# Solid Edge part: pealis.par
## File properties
Author: Cymax
Template: Normal.par
Last saved by: Cymax
Revision: 21
Application: Solid Edge
Accuracy: 0,990
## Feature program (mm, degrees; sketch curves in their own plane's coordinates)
sketch used by "unnamed Protrusion 1" plane through (0, 0, 0) normal (0, 0, 1) x-axis (1, 0, 0)
  line (-3600, 500) -> (-3600, -500)
  line (1000, 1000) -> (-1000, 1000)
  line (1000, -1000) -> (-1000, -1000)
  arc centre (1000, -2880) radius 3880 from (1000, 1000) to (3600, 0) cw
  arc centre (1000, 2880) radius 3880 from (1000, -1000) to (3600, 0) ccw
  arc centre (-1000, -6010) radius 7010 from (-1000, 1000) to (-3600, 500) ccw
  arc centre (-1000, 6010) radius 7010 from (-1000, -1000) to (-3600, -500) cw
extrude "unnamed Protrusion 1" add finite 45 along -normal
logasc func "Lip_Groove_1"  LipOrGrooveWidth = 40 mm; LipOrGrooveHeight = 100 mm
fillet "Round_5" radius 130
sketch for "ExtrudedProtrusion_4" plane through (-26.1302, 0, 0) normal (0, 0, 1) x-axis (-1, 0, 0)
  line (0, 0) -> (0, 0)
  line (-1896.6609, -700) -> (1544.4006, -720.5308)
  line (-1896.6609, 700) -> (-1896.6609, -700)
  line (1544.4006, 720.5308) -> (-1896.6609, 700)
  line (1544.4006, 435) -> (1544.4006, 720.5308)
  line (2940.9751, 435) -> (1544.4006, 435)
  line (2940.9751, -435) -> (2940.9751, 435)
  line (2940.9751, -435) -> (1544.4006, -435)
  line (1544.4006, -435) -> (1544.4006, -720.5308)
extrude "ExtrudedProtrusion_4" add finite 1000 along +normal
sketch for "ExtrudedCutout_3" plane through (0, 0, 0) normal (1, 0, 0) x-axis (0, 1, 0)
  line (745.757, 317.5672) -> (849.4238, 317.5672)
  line (745.757, 317.5672) -> (744.0159, 324.6437)
  arc centre (-453.8381, 29.9336) radius 1233.5754 from (315.9537, 993.8469) to (744.0159, 324.6437) cw
  line (315.9537, 993.8469) -> (170.103, 1110.3249)
  line (-170.103, 1110.3249) -> (170.103, 1110.3249)
  line (-316.9039, 993.0881) -> (-170.103, 1110.3249)
  arc centre (450.6568, 31.9686) radius 1230 from (-743.7254, 325.8245) to (-316.9039, 993.0881) cw
  line (-745.757, 317.5672) -> (-743.7254, 325.8245)
  line (-745.757, 317.5672) -> (-842.6011, 317.5672)
extrude "ExtrudedCutout_3" cut finite 7010.3265 symmetric
sketch for "unnamed Cutout 1" plane through (0, 0, 0) normal (0, -1, 0) x-axis (1, 0, 0)
  line (1957.4005, 0) -> (2691.2115, 297.8266)
  arc centre (-1595.7152, -3073.6527) radius 4698.0818 from (278.8141, 1234.26) to (1957.4005, 0) cw
  line (278.8141, 1234.26) -> (278.8141, 2014.4516)
  line (-2000.4389, 1220.5533) -> (278.8141, 2014.4516)
  line (-2417.9781, 349.241) -> (-2000.4389, 1220.5533)
  line (-3102.9585, 349.241) -> (-2417.9781, 349.241)
extrude "unnamed Cutout 1" cut finite 1529.4835 symmetric
sketch for "ExtrudedCutout_6" plane through (0, 0, 0) normal (0, -1, 0) x-axis (1, 0, 0)
  line (-2132.8174, 356.3644) -> (-1980.9087, 356.3644)
  line (-1980.9087, 356.3644) -> (-1980.9087, 456.1988)
  line (-1980.9087, 456.1988) -> (-1891.0829, 456.1988)
  line (-1891.0829, 456.1988) -> (-1891.0829, 563.1934)
  line (-1891.0829, 563.1934) -> (-1781.2573, 563.1934)
  line (-1781.2573, 563.1934) -> (-1781.2573, 661.8189)
  line (-1781.2573, 661.8189) -> (-1681.4316, 661.8189)
  line (-1681.4316, 661.8189) -> (-1681.4316, 754.1643)
  line (-1681.4316, 754.1643) -> (-1551.2242, 754.1643)
  line (-1551.2242, 754.1643) -> (-1551.2242, 867.0108)
  line (-1551.2242, 867.0108) -> (-1453.5417, 867.0108)
  line (-1453.5417, 867.0108) -> (-1453.5417, 1000.2115)
extrude "ExtrudedCutout_6" cut finite 250.1957 symmetric
thinwall "Thinwall_7"  Thickness = 250 mm
sketch used by "unnamed Cutout 2" plane through (0, 0, -45) normal (0, 0, -1) x-axis (-1, 0, 0)
extrude "unnamed Cutout 2" cut to key point along -normal
chamfer "Chamfer_7" setback 85
fillet "Round_6" radius 200
sketch for "ExtrudedCutout_9" plane through (0, 0, -45) normal (0, 0, -1) x-axis (-1, 0, 0)
extrude "ExtrudedCutout_9" cut finite 1496.2197 along -normal
swept protrusion "SweptProtrusion_6"
helix protrusion "HelixProtrusion_1"  Pitch = 50 mm
sketch for "unnamed Protrusion 2" plane through (0, 0, -45) normal (0, 0, -1) x-axis (-1, 0, 0)
  arc centre (-1000, 2880) radius 3880 from (-3505.0582, -82.9518) to (-3600, 0) cw
  arc centre (-1000, -2880) radius 3880 from (-3505.0582, 82.9518) to (-3600, 0) ccw
  line (-3505.0582, 82.9518) -> (-3505.0582, -82.9518)
extrude "unnamed Protrusion 2" add to key point along +normal
fillet "Round_7" radius 20
sketch for "ExtrudedCutout_10" plane through (-26.1302, 0, 0) normal (0, 0, 1) x-axis (-1, 0, 0)
  arc centre (-1026.1302, 2880) radius 3780 from (-1026.1302, -900) to (-3474.3948, 0) cw
  arc centre (-1026.1302, -2880) radius 3780 from (-1026.1302, 900) to (-3474.3948, 0) ccw
  line (-1026.1302, 900) -> (973.8698, 900)
  arc centre (973.8698, -6010) radius 6910 from (973.8698, 900) to (3473.8698, 431.9019) cw
  line (3473.8698, -431.9019) -> (3473.8698, 431.9019)
  arc centre (973.8698, 6010) radius 6910 from (973.8698, -900) to (3473.8698, -431.9019) ccw
  line (-1026.1302, -900) -> (973.8698, -900)
extrude "ExtrudedCutout_10" cut finite 80 symmetric
sketch for "ExtrudedProtrusion_8" #1 plane through (0, 0, -45) normal (0, 0, -1) x-axis (-1, 0, 0)
  circle centre (1600, -600) radius 75
sketch for "ExtrudedProtrusion_8" #2 plane through (0, 0, -45) normal (0, 0, -1) x-axis (-1, 0, 0)
  circle centre (1600, 600) radius 75
sketch for "ExtrudedProtrusion_8" #3 plane through (0, 0, -45) normal (0, 0, -1) x-axis (-1, 0, 0)
  circle centre (-1600, 600) radius 75
sketch for "ExtrudedProtrusion_8" #4 plane through (0, 0, -45) normal (0, 0, -1) x-axis (-1, 0, 0)
  circle centre (-1600, -600) radius 75
extrude "ExtrudedProtrusion_8" add finite 100 along +normal
sketch for "ExtrudedProtrusion_9" plane through (-4144.3179, 0, -757.9714) normal (-0.681543, 0, -0.731778) x-axis (0, 1, 0)
  circle centre (0, 0) radius 20
extrude "ExtrudedProtrusion_9" add to key point along -normal  Profile_Plane1_FractionOfCurve = 0
sketch for "ExtrudedProtrusion_10" plane through (-3809.9756, 0, -398.9857) normal (-0.731778, 0, 0.681543) x-axis (0, 1, 0)
  line (-5, 490.5665) -> (5, 490.5665)
  line (5, 490.5665) -> (5, -209.4335)
  line (5, -209.4335) -> (-5, -209.4335)
  line (-5, -209.4335) -> (-5, 490.5665)
extrude "ExtrudedProtrusion_10" add finite 30 along +normal
Other named dimensions: "ExtrudedSurface_3": FiniteDepth = 3246.0356 mm | "ExtrudedSurface_4": FiniteDepth = 2943.7397 mm | "ExtrudedSurface_5": FiniteDepth = 9148.0586 mm
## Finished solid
Body 1: sheet body, 1 face, 4 edges, 4 vertices.
  Faces by surface: plane 1
  Edges by curve: line 4
Body 2: sheet body, 1 face, 4 edges, 4 vertices.
  Faces by surface: cylinder 1
  Edges by curve: circle 2, line 2
Body 3: sheet body, 3 faces, 9 edges, 6 vertices.
  Faces by surface: cylinder 2, plane 1
  Edges by curve: line 5, circle 4
Body 4: solid body, 113 faces, 292 edges, 185 vertices, 2 separate solids.
  Faces by surface: plane 79, cylinder 26, spline 5, torus 2, blend 1
  Edges by curve: line 198, circle 56, intersection 24, ellipse 14
Bounding box of the edges (mm; curved faces can reach further): 8447.125 x 9148.059 x 4246.036, from (-4166.2712, -4574.0293, -3246.0356) to (4280.8539, 4574.0293, 1000).
Cylindrical faces by radius (mm): R20 x3, R75 x5, R130 x2, R200 x2, R980 x1, R983.5754 x1, R1230 x1, R1233.5754 x1, R2622.1532 x2, R2843.0979 x1, R3780 x2, R3880 x2, R4448.0818 x1, R4698.0818 x1, R6910 x2, R7010 x2
Toroidal faces (ring radius, tube radius in mm): R3860 r20 x2
Planar faces by outward normal: +x 10, +y 8, +z 10, -x 13, -y 8, -z 14, oblique 16
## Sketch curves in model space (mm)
line (-3475.6333, 0, -40) -> (-4144.3179, 0, -757.9714)
arc centre (-1000, 6010, 0) radius 6910 from (-1000, -900, 0) through (-2271.7228, -781.9674, 0) to (-3500, -431.9019, 0)
line (1000, -900, 0) -> (-1000, -900, 0)
arc centre (1000, 2880, 0) radius 3780 from (1000, -900, 0) through (2304.2239, -667.8726, 0) to (3448.2647, 0, 0)
arc centre (1000, -2880, 0) radius 3780 from (1000, 900, 0) through (2304.2239, 667.8726, 0) to (3448.2647, 0, 0)
line (1000, 900, 0) -> (-1000, 900, 0)
arc centre (-1000, -6010, 0) radius 6910 from (-1000, 900, 0) through (-2271.7228, 781.9674, 0) to (-3500, 431.9019, 0)
line (-3500, 431.9019, 0) -> (-3500, -431.9019, 0)
arc centre (1000, 2880, -45) radius 3880 from (3505.0582, -82.9518, -45) through (3552.8661, -41.8615, -45) to (3600, 0, -45)
line (3505.0582, 82.9518, -45) -> (3505.0582, -82.9518, -45)
arc centre (1000, -2880, -45) radius 3880 from (3505.0582, 82.9518, -45) through (3552.8661, 41.8615, -45) to (3600, 0, -45)
circle centre (3527.4612, 0, -56.5123) radius 15.57
line (3548.2982, 0, -66.3323) -> (3747.8738, 0, -624.2734)
line (-2873.6578, 425, -45) -> (-2873.6578, -425, -45)
line (-2873.6578, -425, -45) -> (-1845.1517, -425, -45)
line (-1845.1517, -425, -45) -> (-1845.1517, 425, -45)
line (-1845.1517, 425, -45) -> (-2873.6578, 425, -45)
line (1986.0273, 683.172, 0) -> (1986.0273, -668.4534, 0)
arc centre (1986.0273, 1953.6998, 0) radius 2622.1532 from (1986.0273, -668.4534, 0) through (2927.3254, -493.6754, 0) to (3743.1402, 7.3593, 0)
arc centre (1986.0273, -1938.9812, 0) radius 2622.1532 from (3743.1402, 7.3593, 0) through (2927.3254, 508.3939, 0) to (1986.0273, 683.172, 0)
circle centre (1600, 600, -45) radius 75
circle centre (1600, -600, -45) radius 75
circle centre (-1600, 600, -45) radius 75
circle centre (-1600, -600, -45) radius 75
arc centre (4280.8539, 0, 2142.9649) radius 2843.0979 from (2412.4569, 0, 0) through (3283.22, 0, -519.3522) to (4280.8539, 0, -700.133)
line (0, 1000, 0) -> (0, -1000, 0)
line (-3600, 0, 0) -> (3600, 0, 0)
arc centre (-1000, 6010, 0) radius 7010 from (-1000, -1000, 0) through (-2323.8202, -873.8652, 0) to (-3600, -500, 0)
line (1000, -1000, 0) -> (-1000, -1000, 0)
arc centre (1000, 2880, 0) radius 3880 from (1000, -1000, 0) through (2392.8388, -741.381, 0) to (3600, 0, 0)
arc centre (1000, -2880, 0) radius 3880 from (1000, 1000, 0) through (2392.8388, 741.381, 0) to (3600, 0, 0)
line (1000, 1000, 0) -> (-1000, 1000, 0)
arc centre (-1000, -6010, 0) radius 7010 from (-1000, 1000, 0) through (-2323.8202, 873.8652, 0) to (-3600, 500, 0)
line (-3600, 500, 0) -> (-3600, -500, 0)
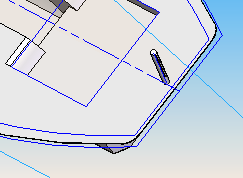
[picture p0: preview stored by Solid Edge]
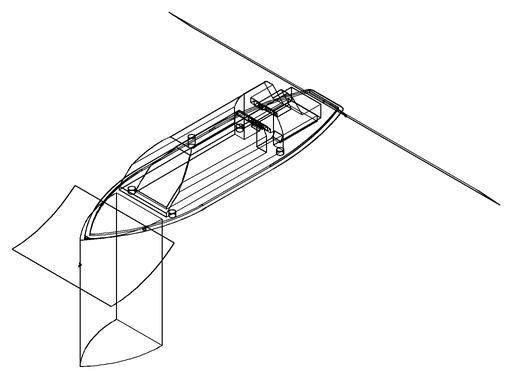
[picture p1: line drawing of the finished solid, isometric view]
